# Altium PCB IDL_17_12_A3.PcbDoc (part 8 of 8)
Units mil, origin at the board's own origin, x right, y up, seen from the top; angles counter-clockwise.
Board outline 5119.97 x 10350 mil, 6 copper layers (Top Signal, 3.3 Volt, GND, 5 Volt, Split Plane, Bot Signal), stack 66.2 mil thick; 510 components, 178 nets, 2317 pads, 385 vias.
Unrouted connection lines stored in the file: 1.
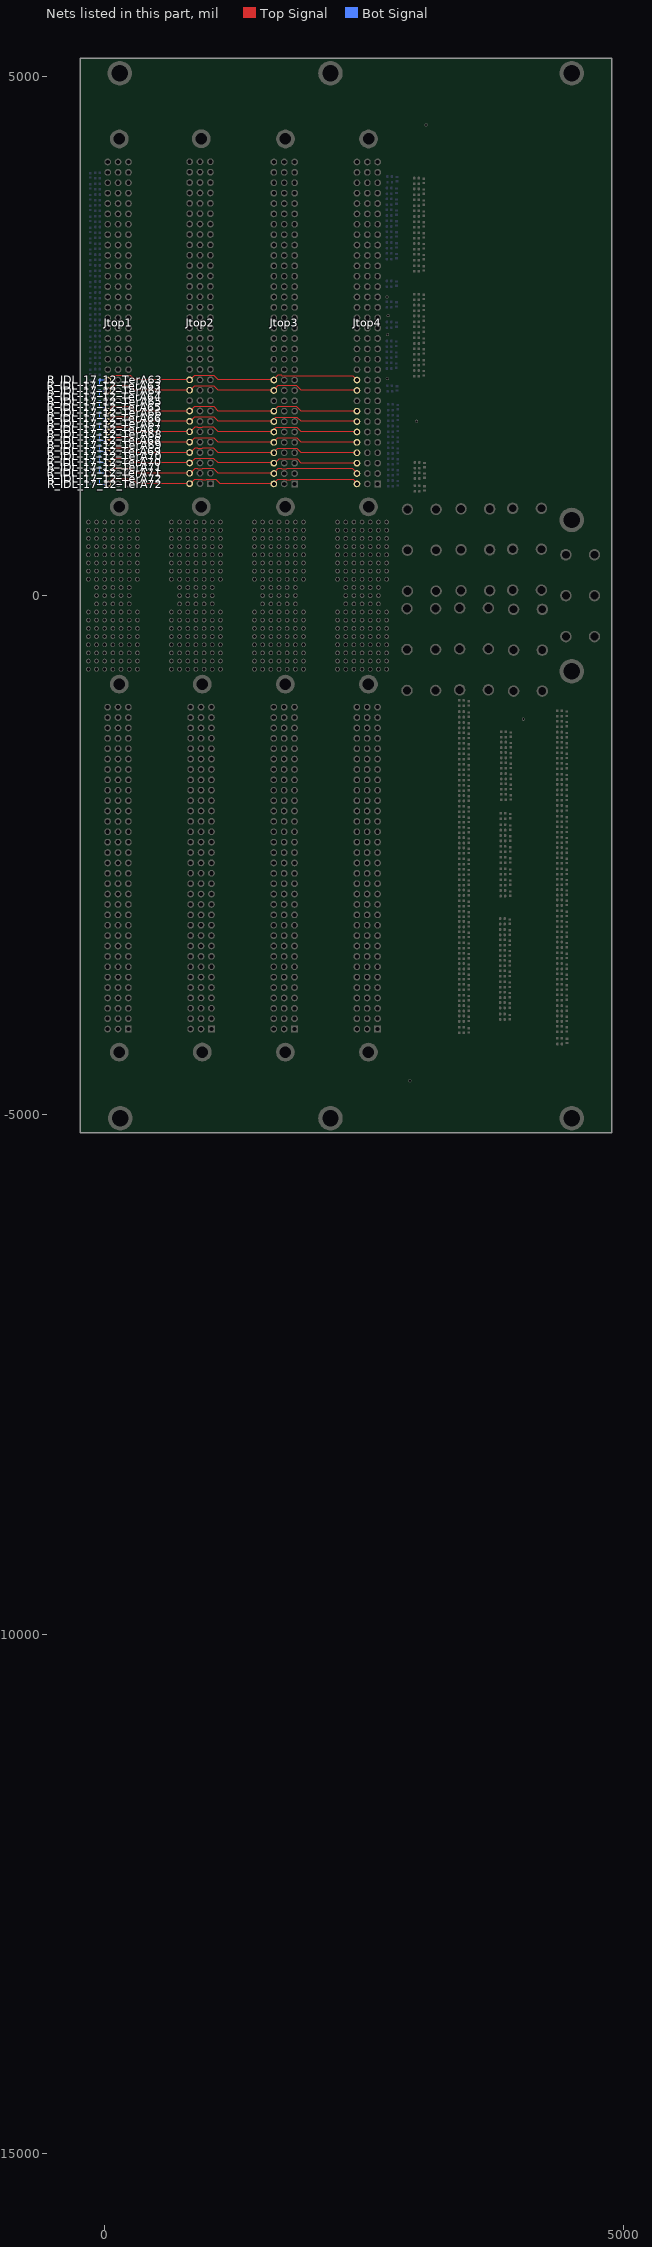
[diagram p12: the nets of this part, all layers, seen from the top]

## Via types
v1: diameter 25.59, hole 11.81, Top Signal to Bot Signal, 385 vias

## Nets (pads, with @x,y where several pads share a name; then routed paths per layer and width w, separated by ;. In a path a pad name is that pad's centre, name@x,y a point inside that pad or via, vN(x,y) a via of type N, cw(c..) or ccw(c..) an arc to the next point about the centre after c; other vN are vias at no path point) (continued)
JT63: Jtop1.C11 Jtop2.C11 Jtop3.C11 Jtop4.C11 R1R_IDL_17_12_TerA63.1 R2R_IDL_17_12_TerA63.2 | length 2657.8
  Top Signal w8: Jtop1.C11@28.79,2082.06 71.27,2124.54 246.39,2124.54 288.45,2082.48 828.72,2082.48 869.23,2122.99 893.67,2122.99 894.79,2121.87 941.58,2121.87 942.7,2122.99 1048.29,2122.99 1088.8,2082.48 1628.3,2082.48 1628.72,2082.06 1672.88,2126.22 1699.42,2126.22 1705.88,2119.76 2391.03,2119.76 Jtop4.C11@2428.72,2082.06
  Bot Signal w8: R2R_IDL_17_12_TerA63.2@-47.49,2021.93 -47.49,2076.07 R1R_IDL_17_12_TerA63.1@-46.62,2076.95 28.57,2076.95 Jtop1.C11@29.28,2076.24 ; Jtop4.C11@2429.28,2076.24 Jtop4.C11@2449.3,2076.24
JT64: Jtop1.C10 Jtop2.C10 Jtop3.C10 Jtop4.C10 R1R_IDL_17_12_TerA64.1 R2R_IDL_17_12_TerA64.2 | length 2662.5
  Top Signal w8: Jtop1.C10@28.79,1982.06 71.27,2024.54 246.39,2024.54 288.45,1982.48 828.72,1982.48 869.23,2022.99 1048.29,2022.99 1088.8,1982.48 1628.3,1982.48 1628.72,1982.06 1672.52,2025.86 1705.05,2025.86 1705.33,2025.58 1752.12,2025.58 1752.4,2025.86 1845,2025.86 1888.8,1982.06 Jtop4.C10@2428.72,1982.06
  Bot Signal w8: R2R_IDL_17_12_TerA64.2@-47.49,1916.93 -46.62,1944.23 R1R_IDL_17_12_TerA64.1@-46.62,1971.95 24.99,1971.95 Jtop1.C10@29.28,1976.24 ; Jtop4.C10@2429.28,1976.24 Jtop4.C10@2453.93,1976.24
JT65: Jtop1.C8 Jtop2.C8 Jtop3.C8 Jtop4.C8 R1R_IDL_17_12_TerA65.1 R2R_IDL_17_12_TerA65.2 | length 2672.6
  Top Signal w8: Jtop1.C8@28.79,1782.06 71.27,1824.54 246.39,1824.54 288.45,1782.48 828.72,1782.48 869.23,1822.99 1048.29,1822.99 1088.8,1782.48 1628.3,1782.48 1628.72,1782.06 1672.52,1825.86 1705.05,1825.86 1705.33,1825.58 1752.12,1825.58 1752.4,1825.86 1845,1825.86 1888.8,1782.06 Jtop4.C8@2428.72,1782.06
  Bot Signal w8: R1R_IDL_17_12_TerA65.1@-46.62,1866.95 -46.62,1812.81 R2R_IDL_17_12_TerA65.2@-47.49,1811.93 -6.41,1811.93 Jtop1.C8@29.28,1776.24 ; Jtop4.C8@2429.28,1776.24 Jtop4.C8@2449.77,1776.24
JT66: Jtop1.C7 Jtop2.C7 Jtop3.C7 Jtop4.C7 R1R_IDL_17_12_TerA66.1 R2R_IDL_17_12_TerA66.2 | length 2642.8
  Top Signal w8: Jtop1.C7@28.79,1682.06 71.27,1724.54 246.39,1724.54 288.45,1682.48 828.72,1682.48 867.06,1720.83 940.54,1720.83 941.62,1721.9 1049.38,1721.9 1088.8,1682.48 1609.02,1682.48 1645.37,1718.84 1852.02,1718.84 1888.8,1682.06 Jtop4.C7@2428.72,1682.06
  Bot Signal w8: R1R_IDL_17_12_TerA66.1@-46.62,1761.95 -46.62,1707.81 R2R_IDL_17_12_TerA66.2@-47.49,1706.93 -1.41,1706.93 Jtop1.C7@29.28,1676.24
JT67: Jtop1.C6 Jtop2.C6 Jtop3.C6 Jtop4.C6 R1R_IDL_17_12_TerA67.1 R2R_IDL_17_12_TerA67.2 | length 2672.9
  Top Signal w8: Jtop1.C6@28.79,1582.06 71.27,1624.54 246.39,1624.54 288.45,1582.48 828.72,1582.48 871.55,1625.31 891.35,1625.31 894.79,1621.87 941.58,1621.87 945.03,1625.31 1045.97,1625.31 1088.8,1582.48 1615.4,1582.48 1653.69,1620.77 1704.87,1620.77 1705.88,1619.76 1752.67,1619.76 1753.69,1620.77 1850.09,1620.77 1888.8,1582.06 Jtop4.C6@2428.72,1582.06
  Bot Signal w8: R1R_IDL_17_12_TerA67.1@-46.62,1656.95 -46.62,1629.23 -47.49,1628.36 R2R_IDL_17_12_TerA67.2@-47.49,1601.93 3.59,1601.93 Jtop1.C6@29.28,1576.24 ; Jtop4.C6@2429.28,1576.24 Jtop4.C6@2453.41,1576.24
JT68: Jtop1.C5 Jtop2.C5 Jtop3.C5 Jtop4.C5 R1R_IDL_17_12_TerA68.1 R2R_IDL_17_12_TerA68.2 | length 2660.1
  Top Signal w8: Jtop1.C5@28.79,1482.06 71.27,1524.54 246.39,1524.54 288.45,1482.48 828.72,1482.48 868.05,1521.81 1049.47,1521.81 1088.8,1482.48 1628.3,1482.48 1628.72,1482.06 1665.77,1519.11 1851.75,1519.11 1888.8,1482.06 Jtop4.C5@2428.72,1482.06
  Bot Signal w8: R1R_IDL_17_12_TerA68.1@-46.62,1551.95 -46.62,1524.23 -47.49,1523.36 R2R_IDL_17_12_TerA68.2@-47.49,1496.93 8.59,1496.93 Jtop1.C5@29.28,1476.24 ; Jtop4.C5@2429.28,1476.24 Jtop4.C5@2450.23,1476.24
JT69: Jtop1.C4 Jtop2.C4 Jtop3.C4 Jtop4.C4 R1R_IDL_17_12_TerA69.1 R2R_IDL_17_12_TerA69.2 | length 2642.3
  Top Signal w8: Jtop1.C4@28.79,1382.06 71.27,1424.54 246.39,1424.54 288.45,1382.48 828.72,1382.48 871.2,1424.96 891.7,1424.96 894.79,1421.87 941.58,1421.87 944.68,1424.96 1046.32,1424.96 1088.8,1382.48 1628.3,1382.48 1628.72,1382.06 1665.84,1419.18 1851.68,1419.18 1888.8,1382.06 Jtop4.C4@2428.72,1382.06
  Bot Signal w8: R1R_IDL_17_12_TerA69.1@-46.62,1446.95 -47.49,1446.07 R2R_IDL_17_12_TerA69.2@-47.49,1391.93 13.59,1391.93 Jtop1.C4@29.28,1376.24
JT70: Jtop1.C3 Jtop2.C3 Jtop3.C3 Jtop4.C3 R1R_IDL_17_12_TerA70.1 R2R_IDL_17_12_TerA70.2 | length 2641.2
  Top Signal w8: Jtop1.C3@28.79,1282.06 71.27,1324.54 246.39,1324.54 288.45,1282.48 828.72,1282.48 871.2,1324.96 891.7,1324.96 894.79,1321.87 941.58,1321.87 944.68,1324.96 1046.32,1324.96 1088.8,1282.48 1628.3,1282.48 1628.72,1282.06 1643.2,1282.06 1679.85,1318.72 1746.87,1318.72 1748.59,1317.01 1809.97,1317.01 1811.68,1318.72 1852.14,1318.72 1888.8,1282.06 Jtop4.C3@2428.72,1282.06
  Bot Signal w8: R1R_IDL_17_12_TerA70.1@-46.62,1341.95 -46.62,1287.81 R2R_IDL_17_12_TerA70.2@-47.49,1286.93 18.59,1286.93 Jtop1.C3@29.28,1276.24
JT71: Jtop1.C2 Jtop2.C2 Jtop3.C2 Jtop4.C2 R1R_IDL_17_12_TerA71.1 R2R_IDL_17_12_TerA71.2 | length 2669.1
  Top Signal w8: Jtop1.C2@28.79,1182.06 71.27,1224.54 246.39,1224.54 288.45,1182.48 828.72,1182.48 871.2,1224.96 891.7,1224.96 894.79,1221.87 941.58,1221.87 944.68,1224.96 1046.32,1224.96 1088.8,1182.48 1628.3,1182.48 1628.72,1182.06 1671.2,1224.54 1701.1,1224.54 1705.88,1219.76 1752.67,1219.76 1757.46,1224.54 2386.24,1224.54 Jtop4.C2@2428.72,1182.06
  Bot Signal w8: R1R_IDL_17_12_TerA71.1@-46.62,1236.95 -47.49,1236.07 R2R_IDL_17_12_TerA71.2@-47.49,1181.93 23.59,1181.93 Jtop1.C2@29.28,1176.24 ; Jtop4.C2@2429.28,1176.24 Jtop4.C2@2451.87,1176.24
JT72: Jtop1.C1 Jtop2.C1 Jtop3.C1 Jtop4.C1 R1R_IDL_17_12_TerA72.1 R2R_IDL_17_12_TerA72.2 | length 2647.7
  Top Signal w8: Jtop1.C1@28.79,1082.06 71.27,1124.54 265.41,1124.54 307.47,1082.48 828.72,1082.48 867.06,1120.83 935.78,1120.83 940.03,1116.58 977.32,1116.58 981.57,1120.83 1069.48,1120.83 1107.82,1082.48 1628.3,1082.48 1628.72,1082.06 1665.37,1118.72 1746.87,1118.72 1749.27,1116.32 1790.26,1116.32 1792.66,1118.72 2392.07,1118.72 Jtop4.C1@2428.72,1082.06
  Bot Signal w8: R1R_IDL_17_12_TerA72.1@-46.63,1126.4 -46.63,1072.16 R2R_IDL_17_12_TerA72.2@-46.36,1071.89 24.93,1071.89 Jtop1.C1@29.28,1076.24 ; Jtop4.C1@2429.28,1063.33 Jtop4.C1@2429.28,1076.24
pads on no net: Jbot1.33 Jbot1.34 Jbot2.33 Jbot2.34 Jbot3.33 Jbot3.34 Jbot4.33 Jbot4.34 JMid1.32 JMid1.33 JMid1.34 JMid1.35 JMid1.51 JMid1.52 JMid1.53 JMid1.54 JMid1.89 JMid1.90 JMid1.91 JMid1.92 JMid1.102 JMid1.103 JMid1.104 JMid1.106 JMid1.108 JMid1.109 JMid1.110 JMid1.111 JMid2.32 JMid2.33 JMid2.34 JMid2.35 JMid2.51 JMid2.52 JMid2.53 JMid2.54 JMid2.89 JMid2.90 JMid2.91 JMid2.92 JMid2.102 JMid2.103 JMid2.104 JMid2.106 JMid2.108 JMid2.109 JMid2.110 JMid2.111 JMid3.32 JMid3.33 JMid3.34 JMid3.35 JMid3.51 JMid3.52 JMid3.53 JMid3.54 JMid3.89 JMid3.90 JMid3.91 JMid3.92 JMid3.102 JMid3.103 JMid3.104 JMid3.106 JMid3.108 JMid3.109 JMid3.110 JMid3.111 JMid4.32 JMid4.33 JMid4.34 JMid4.35 JMid4.51 JMid4.52 JMid4.53 JMid4.54 JMid4.89 JMid4.90 JMid4.91 JMid4.92 JMid4.102 JMid4.103 JMid4.104 JMid4.106 JMid4.108 JMid4.109 JMid4.110 JMid4.111 Jtop1.33 Jtop1.34 Jtop2.33 Jtop2.34 Jtop3.33 Jtop3.34 Jtop4.33 Jtop4.34

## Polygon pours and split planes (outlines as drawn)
3V3 on 3.3 Volt (split plane): 4862.88,-5152.9 -215.91,-5152.9 -215.91,5156.9 4862.88,5156.9
GND on GND (split plane): 4862.88,-5152.9 -216.9,-5152.9 -216.9,5156.9 4862.88,5156.9
5V on 5 Volt (split plane): 4862.88,-5152.9 -215.91,-5152.9 -215.91,5156.9 4862.88,5156.9
no net on Split Plane (split plane): 4810.9,4255.78 4810.9,-471.58 4772.4,-510.07 4394.09,-510.07 4326.93,-442.91 4326.93,4079.79 4326.59,4082.4 4325.58,4084.84 4323.98,4086.92 4221.03,4189.87 4218.94,4191.48 4216.51,4192.48 4213.9,4192.83 2648,4192.83 2645.39,4192.48 2642.96,4191.48 2640.87,4189.87 2439.11,3988.11 2411.18,3988.11 2410.24,3988.5 2407.63,3988.85 2302.7,3988.85 2109.93,4181.62 2107.84,4183.22 2105.41,4184.23 2102.8,4184.57 1830.07,4184.57 1827.46,4184.23 1826.75,4183.93 1825.03,4183.22 1822.94,4181.62 1644.3,4002.98 1481.72,4002.98 1306.23,4178.47 1304.15,4180.07 1301.71,4181.08 1299.1,4181.42 1011.18,4181.42 1008.57,4181.08 1007.85,4180.78 1006.13,4180.07 1004.05,4178.47 867.19,4041.61 813.48,3987.91 728.16,3987.91 533.24,4182.83 531.15,4184.44 528.71,4185.44 526.1,4185.79 221.29,4185.79 218.68,4185.44 217.47,4184.94 216.25,4184.44 214.16,4182.83 24.04,3992.72 -74.26,4091.02 -74.26,4582.63 87.1,4744 4322.68,4744
no net on Split Plane (split plane): 4306.76,4075.61 4306.76,-27.33 3811.52,-27.33 3712.49,71.7 3712.49,1120.64 3712.14,1123.26 3711.13,1125.69 3709.53,1127.78 3254.43,1582.88 3252.34,1584.48 3249.91,1585.49 3247.3,1585.83 29.28,1585.83 27.79,1585.64 27.4,1586.57 25.8,1588.65 -82.28,1696.74 -84.37,1698.34 -84.67,1698.47 -84.67,3851.44 -84.37,3851.57 -82.28,3853.17 30.91,3966.37 31.89,3966.49 34.32,3967.5 36.41,3969.1 38.01,3971.19 39.02,3973.63 39.37,3976.24 39.02,3978.85 38.93,3979.07 225.47,4165.62 521.93,4165.62 716.85,3970.69 718.94,3969.08 720.37,3968.49 721.38,3968.08 723.99,3967.73 817.66,3967.73 820.27,3968.08 822.71,3969.08 824.79,3970.69 881.45,4027.35 1015.36,4161.25 1294.92,4161.25 1470.41,3985.76 1472.5,3984.16 1474.94,3983.15 1477.55,3982.8 1653.03,3982.8 1655.64,3983.15 1658.07,3984.16 1660.16,3985.76 1661.76,3987.85 1662.77,3990.28 1663.12,3992.89 1663.07,3993.22 1834.25,4164.4 2098.62,4164.4 2291.39,3971.63 2293.48,3970.02 2294.7,3969.52 2295.91,3969.02 2298.52,3968.67 2404.81,3968.67 2405.75,3968.28 2408.36,3967.94 2443.29,3967.94 2445.9,3968.28 2448.33,3969.29 2450.42,3970.9 2652.18,4172.65 4209.72,4172.65
-3V3 on Split Plane (split plane): 2758.31,99.98 2758.31,39.27 2758.66,36.66 2759.67,34.23 2761.27,32.14 2848.41,-55 2849.39,-55.75 2850.37,-56.53 2850.44,-56.56 2850.5,-56.6 2851.65,-57.08 2852.79,-57.57 2852.86,-57.58 2852.93,-57.61 2854.16,-57.77 2855.39,-57.95 2908.87,-58.74 2908.94,-58.73 2909.02,-58.74 3325.16,-58.74 3327.77,-58.4 3330.2,-57.39 3332.29,-55.79 3427.02,38.94 3542.81,-76.85 3542.81,-768.37 3054.61,-1256.57 229.31,-1256.57 -147.39,-879.87 -147.39,153.42 -73.52,227.3 2631,227.3
no net on Split Plane (split plane): -85,1467.77 2776.75,1467.77 3421.86,822.66 3421.86,62.31 3320.98,-38.57 2909.09,-38.57 2859.78,-37.84 2778.49,43.45 2778.49,104.16 2778.14,106.77 2777.14,109.21 2775.53,111.29 2642.31,244.52 2640.22,246.12 2637.79,247.13 2635.18,247.47 -75.6,247.47 -149.83,321.7 -149.83,1402.94 -149.84,1403.04 -85.1,1467.78
no net on Split Plane (split plane): 4862.88,-5152.9 -216.9,-5152.9 -216.9,5156.9 4862.88,5156.9

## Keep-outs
Keep-Out Layer:
  lines w20: -237,-5173 -237,5177

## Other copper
3.3 Volt (plane layer: these items are gaps in the copper):
  lines w20: -226,-5162 -226,5166
5 Volt (plane layer: these items are gaps in the copper):
  lines w20: -226,-5162 -226,5166
Split Plane (plane layer: these items are gaps in the copper):
  lines w20: -161.26,1405.89 -86.34,1480.81 ; -159.92,1402.94 -159.92,317.52 -79.78,237.38 2635.18,237.38 2768.4,104.16 2768.4,39.27 2855.54,-47.87 2909.02,-48.66 3325.16,-48.66 3431.95,58.14 3431.95,826.84 2780.93,1477.86 -85,1477.86 ; -94.76,1692.04 -94.76,3862.73 ; -89.42,1689.61 18.67,1581.52 ; -89.42,3860.3 26.52,3976.24 29.28,3976.24 ; -78.74,236.34 -157.48,157.6 -157.48,-884.05 225.13,-1266.66 3058.78,-1266.66 3552.9,-772.55 3552.9,-72.67 3431.95,48.27 ; 23.75,3978.15 221.29,4175.7 526.1,4175.7 723.99,3977.82 817.66,3977.82 874.32,4034.48 1011.18,4171.33 1299.1,4171.33 1477.55,3992.89 1653.03,3992.89 ; 23.75,3978.75 -84.35,4086.84 -84.35,4586.81 82.92,4754.08 4326.85,4754.08 4820.98,4259.96 4820.98,-475.75 4776.57,-520.16 4389.91,-520.16 4316.84,-447.09 4316.84,4079.79 4213.9,4182.74 2648,4182.74 2443.29,3978.03 2408.36,3978.03 2407.63,3978.76 2298.52,3978.76 2102.8,4174.49 1830.07,4174.49 1650.75,3995.17 ; 29.28,1575.75 3247.3,1575.75 3702.4,1120.64 3702.4,67.52 3807.34,-37.42 4315.22,-37.42

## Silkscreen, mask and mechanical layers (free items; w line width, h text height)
Top Overlay:
  drawing of 160 lines, arcs and shapes, not listed
  text "IDL_17_12 / VME Backplae Rev.A / Designer: Jose Duron" at 3223.2,-4687.76 h60
  text "IDL" at 3398.32,-4827.7 h50
  text "Instrumentation" at 3398.32,-4877.7 h25
  text "Development" at 3398.32,-4917.7 h25
  text "Lab" at 3398.32,-4957.7 h25
Mechanical 2:
  drawing of 252 lines, arcs and shapes, not listed
  text "1" at -13904.31,8306.83 h35
  text "2" at -11929.31,8306.83 h35
  text "3" at -9954.31,8306.83 h35
  text "4" at -7979.31,8306.83 h35
  text "5" at -6004.31,8306.83 h35
  text "6" at -4029.31,8306.83 h35
  text "7" at -2054.31,8306.83 h35
  text "8" at -79.31,8306.83 h35
  text "1" at -14184.39,7643.66 h35
  text "2" at -12209.39,7643.66 h35
  text "3" at -10234.39,7643.66 h35
  text "4" at -8259.39,7643.66 h35
  text "5" at -6284.39,7643.66 h35
  text "6" at -4309.39,7643.66 h35
  text "7" at -2334.39,7643.66 h35
  text "8" at -359.39,7643.66 h35
  text "A" at -14846.86,7349.68 h35
  text "A" at 853.15,7349.68 h35
  text "1" at 2612.73,6786.27 h35
  text "2" at 4587.73,6786.27 h35
  text "3" at 6562.73,6786.27 h35
  text "4" at 8537.73,6786.27 h35
  text "5" at 10512.73,6786.27 h35
  text "6" at 12487.73,6786.27 h35
  text "7" at 14462.73,6786.27 h35
  text "8" at 16437.73,6786.27 h35
  text "A" at -15126.93,6686.51 h35
  text "A" at 573.07,6686.51 h35
  text "1" at -13620.84,6299.24 h35
  text "2" at -11645.84,6299.24 h35
  text "3" at -9670.84,6299.24 h35
  text "4" at -7695.84,6299.24 h35
  text "5" at -5720.84,6299.24 h35
  text "6" at -3745.84,6299.24 h35
  text "7" at -1770.84,6299.24 h35
  text "8" at 204.16,6299.24 h35
  text "A" at 1670.18,5829.12 h35
  text "A" at 17370.18,5829.12 h35
  text "B" at -14846.86,5436.35 h35
  text "B" at 853.15,5436.35 h35
  text "A" at -14563.38,5342.09 h35
  text "A" at 1136.62,5342.09 h35
  text "B" at -15126.93,4773.18 h35
  text "B" at 573.07,4773.18 h35
  text "B" at 1670.18,3915.79 h35
  text "B" at 17370.18,3915.79 h35
  text "C" at -14851.9,3523.01 h35
  text "C" at 848.1,3523.01 h35
  text "B" at -14563.38,3428.76 h35
  text "B" at 1136.62,3428.76 h35
  text "C" at -15131.98,2859.84 h35
  text "C" at 568.02,2859.84 h35
  text "C" at 1665.14,2002.45 h35
  text "C" at 17365.14,2002.45 h35
  text "D" at -14851.9,1609.68 h35
  text "D" at 848.1,1609.68 h35
  text "1" at -9275.06,1545.98 h35
  text "2" at -7300.06,1545.98 h35
  text "3" at -5325.06,1545.98 h35
  text "4" at -3350.06,1545.98 h35
  text "5" at -1375.06,1545.98 h35
  text "6" at 599.94,1545.98 h35
  text "7" at 2574.94,1545.98 h35
  text "8" at 4549.94,1545.98 h35
  text "C" at -14568.43,1515.43 h35
  text "C" at 1131.57,1515.43 h35
  text "D" at -15131.98,946.51 h35
  text "D" at 568.02,946.51 h35
  text "1" at 5628.19,870.06 h35
  text "2" at 7603.19,870.06 h35
  text "3" at 9578.19,870.06 h35
  text "4" at 11553.19,870.06 h35
  text "5" at 13528.19,870.06 h35
  text "6" at 15503.19,870.06 h35
  text "7" at 17478.19,870.06 h35
  text "8" at 19453.19,870.06 h35
  text "A" at -10217.6,588.82 h35
  text "A" at 5482.4,588.82 h35
  text "D" at 1665.14,89.12 h35
  text "D" at 17365.14,89.12 h35
  text "A" at 4685.65,-87.09 h35
  text "A" at 20385.65,-87.09 h35
  text "E" at -14846.86,-303.65 h35
  text "E" at 853.15,-303.65 h35
  text "D" at -14568.43,-397.91 h35
  text "D" at 1131.57,-397.91 h35
  text "E" at -15126.93,-966.82 h35
  text "E" at 573.07,-966.82 h35
  text "B" at -10217.6,-1324.51 h35
  text "B" at 5482.4,-1324.51 h35
  text "E" at 1670.18,-1824.21 h35
  text "E" at 17370.18,-1824.21 h35
  text "B" at 4685.65,-2000.42 h35
  text "B" at 20385.65,-2000.42 h35
  text "F" at -14846.86,-2216.99 h35
  text "F" at 853.15,-2216.99 h35
  text "E" at -14563.38,-2311.24 h35
  text "E" at 1136.62,-2311.24 h35
  text "Designer:" at -5836.63,-2373.65 h100
  text ".Designer" at -5271.63,-2378.65 h100
  text "Revision:" at -4331.63,-2378.65 h100
  text ".RevNum" at -3771.63,-2378.65 h100
  text "File:" at -3331.63,-2378.65 h100
  text ".Pcb_File_Name_No_Path" at -3131.63,-2378.65 h100
  text "Sheet  1 of  1" at -1736.63,-2378.65 h100
  text "Code:" at -1016.63,-2423.65 h100
  text "Drawn By:" at -5836.63,-2493.65 h100
  text ".Drawn_By" at -5271.63,-2493.65 h100
  text "Modif. Date:" at -4331.63,-2498.65 h100
  text "Date" at -3826.63,-2498.65 h100
  text "Variant:" at -3331.63,-2498.65 h100
  text ".VariantName" at -2966.63,-2498.65 h100
  text "ID:" at -1011.63,-2603.65 h100
  text "Approved By:" at -5836.63,-2613.65 h100
  text ".Approved_By" at -5271.63,-2613.65 h100
  text ".Print_Date" at -3884.23,-2618.06 h100
  text "Print Date:" at -4331.63,-2618.65 h100
  text "Signature:" at -3331.63,-2618.65 h100
  text "Size:  A3 H" at -1736.63,-2618.65 h100
  text "Title:" at -5836.63,-2743.65 h100
  text "University of Hawaii at Manoa" at -1010.21,-2751.92 h100
  text "High Energy Physics Group" at -1010.21,-2850.35 h100
  text "F" at -15126.93,-2880.16 h35
  text "F" at 573.07,-2880.16 h35
  text ".Printout_Name" at -5611.63,-2883.65 h160
  text "Instrumentation Development Laboratory" at -1010.21,-2952.71 h100
  text "Designer:" at -6116.71,-3036.82 h100
  text ".Designer" at -5551.71,-3041.82 h100
  text "Revision:" at -4611.71,-3041.82 h100
  text ".RevNum" at -4051.71,-3041.82 h100
  text "File:" at -3611.71,-3041.82 h100
  text ".Pcb_File_Name_No_Path" at -3411.71,-3041.82 h100
  text "Sheet  1 of  1" at -2016.71,-3041.82 h100
  text "1" at -13904.31,-3073.17 h35
  text "2" at -11929.31,-3073.17 h35
  text "3" at -9954.31,-3073.17 h35
  text "4" at -7979.31,-3073.17 h35
  text "5" at -6004.31,-3073.17 h35
  text "6" at -4029.31,-3073.17 h35
  text "7" at -2054.31,-3073.17 h35
  text "8" at -79.31,-3073.17 h35
  text "Code:" at -1296.71,-3086.82 h100
  text "Drawn By:" at -6116.71,-3156.82 h100
  text ".Drawn_By" at -5551.71,-3156.82 h100
  text "Modif. Date:" at -4611.71,-3161.82 h100
  text "Date" at -4106.71,-3161.82 h100
  text "Variant:" at -3611.71,-3161.82 h100
  text ".VariantName" at -3246.71,-3161.82 h100
  text "C" at -10222.65,-3237.84 h35
  text "C" at 5477.35,-3237.84 h35
  text "ID:" at -1291.71,-3266.82 h100
  text "Approved By:" at -6116.71,-3276.82 h100
  text ".Approved_By" at -5551.71,-3276.82 h100
  text ".Print_Date" at -4164.31,-3281.23 h100
  text "Print Date:" at -4611.71,-3281.82 h100
  text "Signature:" at -3611.71,-3281.82 h100
  text "Size:  A3 H" at -2016.71,-3281.82 h100
  text "Title:" at -6116.71,-3406.82 h100
  text "University of Hawaii at Manoa" at -1290.29,-3415.09 h100
  text "High Energy Physics Group" at -1290.29,-3513.52 h100
  text ".Printout_Name" at -5891.71,-3546.82 h160
  text "Instrumentation Development Laboratory" at -1290.29,-3615.88 h100
  text "1" at -14184.39,-3736.34 h35
  text "2" at -12209.39,-3736.34 h35
  text "3" at -10234.39,-3736.34 h35
  text "4" at -8259.39,-3736.34 h35
  text "5" at -6284.39,-3736.34 h35
  text "6" at -4309.39,-3736.34 h35
  text "7" at -2334.39,-3736.34 h35
  text "8" at -359.39,-3736.34 h35
  text "F" at 1670.18,-3737.55 h35
  text "F" at 17370.18,-3737.55 h35
  text "Designer:" at 10680.41,-3894.21 h100
  text ".Designer" at 11245.41,-3899.21 h100
  text "Revision:" at 12185.41,-3899.21 h100
  text ".RevNum" at 12745.41,-3899.21 h100
  text "File:" at 13185.41,-3899.21 h100
  text ".Pcb_File_Name_No_Path" at 13385.41,-3899.21 h100
  text "Sheet  1 of  1" at 14780.41,-3899.21 h100
  text "C" at 4680.6,-3913.75 h35
  text "C" at 20380.6,-3913.75 h35
  text "Code:" at 15500.41,-3944.21 h100
  text "Drawn By:" at 10680.41,-4014.21 h100
  text ".Drawn_By" at 11245.41,-4014.21 h100
  text "Modif. Date:" at 12185.41,-4019.21 h100
  text "Date" at 12690.41,-4019.21 h100
  text "Variant:" at 13185.41,-4019.21 h100
  text ".VariantName" at 13550.41,-4019.21 h100
  text "ID:" at 15505.41,-4124.21 h100
  text "Approved By:" at 10680.41,-4134.21 h100
  text ".Approved_By" at 11245.41,-4134.21 h100
  text "Print Date:" at 12185.41,-4139.21 h100
  text ".Print_Date" at 12632.81,-4138.62 h100
  text "Signature:" at 13185.41,-4139.21 h100
  text "Size:  A3 H" at 14780.41,-4139.21 h100
  text "F" at -14563.38,-4224.57 h35
  text "F" at 1136.62,-4224.57 h35
  text "Title:" at 10680.41,-4264.21 h100
  text "University of Hawaii at Manoa" at 15506.82,-4272.48 h100
  text "High Energy Physics Group" at 15506.82,-4370.91 h100
  text "Designer:" at -5553.16,-4381.24 h100
  text ".Designer" at -4988.16,-4386.24 h100
  text "Revision:" at -4048.16,-4386.24 h100
  text ".RevNum" at -3488.16,-4386.24 h100
  text "File:" at -3048.16,-4386.24 h100
  text ".Pcb_File_Name_No_Path" at -2848.16,-4386.24 h100
  text "Sheet  1 of  1" at -1453.16,-4386.24 h100
  text ".Printout_Name" at 10905.41,-4404.21 h160
  text "Code:" at -733.16,-4431.24 h100
  text "Instrumentation Development Laboratory" at 15506.82,-4473.27 h100
  text "Drawn By:" at -5553.16,-4501.24 h100
  text ".Drawn_By" at -4988.16,-4501.24 h100
  text "Modif. Date:" at -4048.16,-4506.24 h100
  text "Date" at -3543.16,-4506.24 h100
  text "Variant:" at -3048.16,-4506.24 h100
  text ".VariantName" at -2683.16,-4506.24 h100
  text "1" at 2612.73,-4593.73 h35
  text "2" at 4587.73,-4593.73 h35
  text "3" at 6562.73,-4593.73 h35
  text "4" at 8537.73,-4593.73 h35
  text "5" at 10512.73,-4593.73 h35
  text "6" at 12487.73,-4593.73 h35
  text "7" at 14462.73,-4593.73 h35
  text "8" at 16437.73,-4593.73 h35
  text "ID:" at -728.16,-4611.24 h100
  text "Approved By:" at -5553.16,-4621.24 h100
  text ".Approved_By" at -4988.16,-4621.24 h100
  text "Print Date:" at -4048.16,-4626.24 h100
  text ".Print_Date" at -3600.76,-4625.65 h100
  text "Signature:" at -3048.16,-4626.24 h100
  text "Size:  A3 H" at -1453.16,-4626.24 h100
  text "Title:" at -5553.16,-4751.24 h100
  text "University of Hawaii at Manoa" at -726.74,-4759.51 h100
  text "High Energy Physics Group" at -726.74,-4857.93 h100
  text ".Printout_Name" at -5328.16,-4891.24 h160
  text "Instrumentation Development Laboratory" at -726.74,-4960.3 h100
  text "1" at -13620.84,-5080.76 h35
  text "2" at -11645.84,-5080.76 h35
  text "3" at -9670.84,-5080.76 h35
  text "4" at -7695.84,-5080.76 h35
  text "5" at -5720.84,-5080.76 h35
  text "6" at -3745.84,-5080.76 h35
  text "7" at -1770.84,-5080.76 h35
  text "8" at 204.16,-5080.76 h35
  text "D" at -10222.65,-5151.18 h35
  text "D" at 5477.35,-5151.18 h35
  text "D" at 4680.6,-5827.09 h35
  text "D" at 20380.6,-5827.09 h35
  text "E" at -10217.6,-7064.51 h35
  text "E" at 5482.4,-7064.51 h35
  text "E" at 4685.65,-7740.42 h35
  text "E" at 20385.65,-7740.42 h35
  text "F" at -10217.6,-8977.84 h35
  text "F" at 5482.4,-8977.84 h35
  text "Designer:" at -1207.38,-9134.51 h100
  text ".Designer" at -642.38,-9139.51 h100
  text "Revision:" at 297.62,-9139.51 h100
  text ".RevNum" at 857.62,-9139.51 h100
  text "File:" at 1297.62,-9139.51 h100
  text ".Pcb_File_Name_No_Path" at 1497.62,-9139.51 h100
  text "Sheet  1 of  1" at 2892.62,-9139.51 h100
  text "Code:" at 3612.62,-9184.51 h100
  text "Drawn By:" at -1207.38,-9254.51 h100
  text ".Drawn_By" at -642.38,-9254.51 h100
  text "Modif. Date:" at 297.62,-9259.51 h100
  text "Date" at 802.62,-9259.51 h100
  text "Variant:" at 1297.62,-9259.51 h100
  text ".VariantName" at 1662.62,-9259.51 h100
  text "ID:" at 3617.62,-9364.51 h100
  text "Approved By:" at -1207.38,-9374.51 h100
  text ".Approved_By" at -642.38,-9374.51 h100
  text ".Print_Date" at 745.02,-9378.92 h100
  text "Print Date:" at 297.62,-9379.51 h100
  text "Signature:" at 1297.62,-9379.51 h100
  text "Size:  A3 H" at 2892.62,-9379.51 h100
  text "Title:" at -1207.38,-9504.51 h100
  text "University of Hawaii at Manoa" at 3619.04,-9512.78 h100
  text "High Energy Physics Group" at 3619.04,-9611.2 h100
  text ".Printout_Name" at -982.38,-9644.51 h160
  text "F" at 4685.65,-9653.75 h35
  text "F" at 20385.65,-9653.75 h35
  text "Instrumentation Development Laboratory" at 3619.04,-9713.56 h100
  text "Designer:" at 13695.87,-9810.42 h100
  text ".Designer" at 14260.87,-9815.42 h100
  text "Revision:" at 15200.87,-9815.42 h100
  text ".RevNum" at 15760.87,-9815.42 h100
  text "File:" at 16200.87,-9815.42 h100
  text ".Pcb_File_Name_No_Path" at 16400.87,-9815.42 h100
  text "Sheet  1 of  1" at 17795.87,-9815.42 h100
  text "1" at -9275.06,-9834.02 h35
  text "2" at -7300.06,-9834.02 h35
  text "3" at -5325.06,-9834.02 h35
  text "4" at -3350.06,-9834.02 h35
  text "5" at -1375.06,-9834.02 h35
  text "6" at 599.94,-9834.02 h35
  text "7" at 2574.94,-9834.02 h35
  text "8" at 4549.94,-9834.02 h35
  text "Code:" at 18515.87,-9860.42 h100
  text "Drawn By:" at 13695.87,-9930.42 h100
  text ".Drawn_By" at 14260.87,-9930.42 h100
  text "Modif. Date:" at 15200.87,-9935.42 h100
  text "Date" at 15705.87,-9935.42 h100
  text "Variant:" at 16200.87,-9935.42 h100
  text ".VariantName" at 16565.87,-9935.42 h100
  text "ID:" at 18520.87,-10040.42 h100
  text "Approved By:" at 13695.87,-10050.42 h100
  text ".Approved_By" at 14260.87,-10050.42 h100
  text "Print Date:" at 15200.87,-10055.42 h100
  text ".Print_Date" at 15648.27,-10054.83 h100
  text "Signature:" at 16200.87,-10055.42 h100
  text "Size:  A3 H" at 17795.87,-10055.42 h100
  text "Title:" at 13695.87,-10180.42 h100
  text "University of Hawaii at Manoa" at 18522.29,-10188.69 h100
  text "High Energy Physics Group" at 18522.29,-10287.12 h100
  text ".Printout_Name" at 13920.87,-10320.42 h160
  text "Instrumentation Development Laboratory" at 18522.29,-10389.48 h100
  text "1" at 5628.19,-10509.94 h35
  text "2" at 7603.19,-10509.94 h35
  text "3" at 9578.19,-10509.94 h35
  text "4" at 11553.19,-10509.94 h35
  text "5" at 13528.19,-10509.94 h35
  text "6" at 15503.19,-10509.94 h35
  text "7" at 17478.19,-10509.94 h35
  text "8" at 19453.19,-10509.94 h35
Board Outline:
  lines w20: -237,-5173 4880.39,-5173 4880.39,5174.4 4880.55,5174.55 -234.55,5174.55 -237,5177 -237,-5173
Sheet Top:
  lines w3.9: -2026.33,-3719.49 -1926.33,-3719.49 ; -2026.33,-1806.16 -1926.33,-1806.16 ; -2026.33,107.18 -1926.33,107.18 ; -2026.33,2020.51 -1926.33,2020.51 ; -2026.33,3933.84 -1926.33,3933.84 ; -51.33,-5632.82 -51.33,-5532.82 ; -51.33,5747.18 -51.33,5847.18 ; 1923.67,-5632.82 1923.67,-5532.82 ; 1923.67,5747.18 1923.67,5847.18 ; 3898.67,-5632.82 3898.67,-5532.82 ; 3898.67,5747.18 3898.67,5847.18 ; 5873.67,-5632.82 5873.67,-5532.82 ; 5873.67,5747.18 5873.67,5847.18 ; 7848.67,-5632.82 7848.67,-5532.82 ; 7848.67,5747.18 7848.67,5847.18 ; 9823.67,-5632.82 9823.67,-5532.82 ; 9823.67,5747.18 9823.67,5847.18 ; 11798.67,-5632.82 11798.67,-5532.82 ; 11798.67,5747.18 11798.67,5847.18 ; 13673.67,-3719.49 13773.67,-3719.49 ; 13673.67,-1806.16 13773.67,-1806.16 ; 13673.67,107.18 13773.67,107.18 ; 13673.67,2020.51 13773.67,2020.51 ; 13673.67,3933.84 13773.67,3933.84 ; -2026.33,-5632.73 13773.58,-5632.73 13773.58,5847.18 -2026.33,5847.18 -2026.33,-5632.73 ; -1926.07,-5533.02 13673.32,-5533.02 13673.32,5747.47 -1926.07,5747.47 -1926.07,-5533.02
  lines w3.94: 6983.67,-5533.02 6983.67,-4822.82 13673.32,-4822.82 ; 6983.67,-5182.06 13673.67,-5182.06 ; 6983.67,-5062.82 11803.67,-5062.82 ; 6983.67,-4942.82 11803.67,-4942.82 ; 8488.67,-5182.06 8488.67,-4822.82 ; 9488.67,-5182.06 9488.67,-4822.82 ; 11078.67,-5182.06 11078.67,-4822.82 ; 11803.67,-5533.02 11803.67,-4822.82 ; 11803.67,-5002.82 13673.32,-5002.82
  text "1" at -1059.01,5767.66 h35
  text "2" at 915.99,5767.66 h35
  text "3" at 2890.99,5767.66 h35
  text "4" at 4865.99,5767.66 h35
  text "5" at 6840.99,5767.66 h35
  text "6" at 8815.99,5767.66 h35
  text "7" at 10790.99,5767.66 h35
  text "8" at 12765.99,5767.66 h35
  text "A" at -2001.56,4810.51 h35
  text "A" at 13698.45,4810.51 h35
  text "B" at -2001.56,2897.18 h35
  text "B" at 13698.45,2897.18 h35
  text "C" at -2006.6,983.84 h35
  text "C" at 13693.4,983.84 h35
  text "D" at -2006.6,-929.49 h35
  text "D" at 13693.4,-929.49 h35
  text "E" at -2001.56,-2842.82 h35
  text "E" at 13698.45,-2842.82 h35
  text "F" at -2001.56,-4756.16 h35
  text "F" at 13698.45,-4756.16 h35
  text "Designer:" at 7008.67,-4912.82 h100
  text ".Designer" at 7573.67,-4917.82 h100
  text "Revision:" at 8513.67,-4917.82 h100
  text ".RevNum" at 9073.67,-4917.82 h100
  text "File:" at 9513.67,-4917.82 h100
  text ".Pcb_File_Name_No_Path" at 9713.67,-4917.82 h100
  text "Sheet  1 of  1" at 11108.67,-4917.82 h100
  text "Code:" at 11828.67,-4962.82 h100
  text "Drawn By:" at 7008.67,-5032.82 h100
  text ".Drawn_By" at 7573.67,-5032.82 h100
  text "Modif. Date:" at 8513.67,-5037.82 h100
  text "Date" at 9018.67,-5037.82 h100
  text "Variant:" at 9513.67,-5037.82 h100
  text ".VariantName" at 9878.67,-5037.82 h100
  text "ID:" at 11833.67,-5142.82 h100
  text "Approved By:" at 7008.67,-5152.82 h100
  text ".Approved_By" at 7573.67,-5152.82 h100
  text ".Print_Date" at 8961.07,-5157.23 h100
  text "Print Date:" at 8513.67,-5157.82 h100
  text "Signature:" at 9513.67,-5157.82 h100
  text "Size:  A3 H" at 11108.67,-5157.82 h100
  text "Title:" at 7008.67,-5282.82 h100
  text "University of Hawaii at Manoa" at 11835.08,-5291.09 h100
  text "High Energy Physics Group" at 11835.08,-5389.52 h100
  text ".Printout_Name" at 7233.67,-5422.82 h160
  text "Instrumentation Development Laboratory" at 11835.08,-5491.88 h100
  text "1" at -1059.01,-5612.34 h35
  text "2" at 915.99,-5612.34 h35
  text "3" at 2890.99,-5612.34 h35
  text "4" at 4865.99,-5612.34 h35
  text "5" at 6840.99,-5612.34 h35
  text "6" at 8815.99,-5612.34 h35
  text "7" at 10790.99,-5612.34 h35
  text "8" at 12765.99,-5612.34 h35
Drill Drawing:
  drawing of 468 lines, arcs and shapes, not listed
  text "Notes:" at 7727.76,3850.27 h130
  text "1. Board shall be fabricated - performace class II as per IPC-6011 and IPC6012" at 7727.76,3725.27 h100
  text "2.All of bottom edge and sides edges up to 3.2mm of PCB needs to be plated with 35um copper." at 7727.76,3600.27 h100
  text "3. Silkscreen printed on both sides" at 7727.76,3493.78 h100
  text "4. Material: high temperature FR4 class epoxy glass rated UL94V-0. UL symbol and rating shall be marked farside" at 7727.76,3368.78 h100
  text "35um copper for external and internal layers" at 7827.78,3268.78 h100
  text "Must be RoHS compliant and survive a lead-free assembly max reflow of 260 deg C (5 passes)" at 7827.76,3168.78 h100
  text "Td rating: >340 deg C" at 7877.76,3043.78 h100
  text "Tg = 150 deg C (min)" at 7881.79,2933.52 h100
  text "5. Solder mask: SMOBC per IPC-SM-840C, class T must be Rohs compliant, 0.001\" max measured over bare copper plating," at 7727.76,2823.7 h100
  text "must clear all lands as indicated on gerber solder mask layers, color= GREEN" at 7827.76,2723.7 h100
  text "6. Finish: electro-less nickel immersion gold (ENIG), 0.05-0.125um Au over 3-6um Ni - over bare copper only" at 7727.55,2569.88 h100
  text "7. Solderability test: Category 2 of J-STD-003" at 7727.76,2423.7 h100
  text "8. Finished boards shall not have nicks, scratches, voids, exposed copper, poor plating or misdrilled holes" at 7727.76,2273.7 h100
  text "9. All holes sizes are after plating" at 7727.76,2123.7 h100
  text "10. PCB manufacturer may add copper thieving as needed to improve manufacturability," at 7677.76,1973.7 h100
  text "thieving to be 0.030\" round pads at 0.050\" spacing." at 7827.76,1873.7 h100
  text "Thieving will have a minimum of 0.100\" clearance from existing copper and should not be placed under surface mounted devices" at 7827.76,1773.7 h100
  text "11. PCB manufacturer may use tear drops to improve annular rings as long as DRC rules are followed" at 7682.76,1633.7 h100
  text "12. All via connections to power and ground planes are solid" at 7682.76,1493.7 h100
  text "13. All unconnected pads on inner signal layers are removed" at 7682.76,1353.7 h100
  text "14. All finished boards are to be 100% electrically tested" at 7682.78,1213.7 h100
  text "15. Unless otherwise indicated, all linear toleracnes shall be XX.X +/-0.2mm and XX.XX +/- 0.1mm" at 7682.76,1073.7 h100
  text "16. Gerber file GM1 shows board outline (milling line)" at 7682.75,933.68 h100
  text "17. Table 1 shows Layer stack details" at 7682.75,793.67 h100
  text "18. Gerber files GTP ans DBP shows stencil cut out, stencil should be flat with no bent tabs on sides." at 7682.75,636.19 h100
  text "Symbol" at 7589.39,-1333.67 h72
  text "Count" at 8095.27,-1333.67 h72
  text "Hole Size" at 8745.09,-1333.67 h72
  text "Plated" at 9894.76,-1333.67 h72
  text "Hole Type" at 10400.63,-1333.67 h72
  text "Hole Length" at 11134.43,-1333.67 h72
  text "8" at 8095.27,-1483.67 h60
  text "19.69mil (0.500mm)" at 8745.09,-1483.67 h60
  text "PTH" at 9894.76,-1483.67 h60
  text "Round" at 10400.63,-1483.67 h60
  text "-" at 11134.43,-1483.67 h60
  text "9" at 8095.27,-1633.67 h60
  text "157.00mil (3.988mm)" at 8745.09,-1633.67 h60
  text "PTH" at 9894.76,-1633.67 h60
  text "Round" at 10400.63,-1633.67 h60
  text "-" at 11134.43,-1633.67 h60
  text "16" at 8095.27,-1783.67 h60
  text "110.24mil (2.800mm)" at 8745.09,-1783.67 h60
  text "PTH" at 9894.76,-1783.67 h60
  text "Round" at 10400.63,-1783.67 h60
  text "-" at 11134.43,-1783.67 h60
  text "42" at 8095.27,-1933.67 h60
  text "76.00mil (1.930mm)" at 8745.09,-1933.67 h60
  text "PTH" at 9894.76,-1933.67 h60
  text "Round" at 10400.63,-1933.67 h60
  text "-" at 11134.43,-1933.67 h60
  text "385" at 8095.27,-2083.67 h60
  text "11.81mil (0.300mm)" at 8745.09,-2083.67 h60
  text "PTH" at 9894.76,-2083.67 h60
  text "Round" at 10400.63,-2083.67 h60
  text "-" at 11134.43,-2083.67 h60
  text "508" at 8095.27,-2233.67 h60
  text "30.00mil (0.762mm)" at 8745.09,-2233.67 h60
  text "PTH" at 9894.76,-2233.67 h60
  text "Round" at 10400.63,-2233.67 h60
  text "-" at 11134.43,-2233.67 h60
  text "768" at 8095.27,-2383.67 h60
  text "39.37mil (1.000mm)" at 8745.09,-2383.67 h60
  text "PTH" at 9894.76,-2383.67 h60
  text "Round" at 10400.63,-2383.67 h60
  text "-" at 11134.43,-2383.67 h60
  text "1736 Total" at 8095.27,-2533.67 h60
  text "Layer" at 7540.2,-2823.89 h60
  text "Name" at 7950.11,-2823.89 h60
  text "Material" at 8879.85,-2823.89 h60
  text "Thickness" at 9739.62,-2823.89 h60
  text "Constant" at 10389.45,-2823.89 h60
  text "Board Layer Stack" at 10959.32,-2823.89 h60
  text "1" at 7540.2,-2943.89 h60
  text "Top Overlay" at 7950.11,-2943.89 h60
  text "2" at 7540.2,-3063.89 h60
  text "Top Solder" at 7950.11,-3063.89 h60
  text "Solder Resist" at 8879.85,-3063.89 h60
  text "0.40mil" at 9739.62,-3063.89 h60
  text "3.5" at 10389.45,-3063.89 h60
  text "3" at 7540.2,-3183.89 h60
  text "Top Signal" at 7950.11,-3183.89 h60
  text "Copper" at 8879.85,-3183.89 h60
  text "2.70mil" at 9739.62,-3183.89 h60
  text "4" at 7540.2,-3303.89 h60
  text "Dielectric 1" at 7950.11,-3303.89 h60
  text "FR-4" at 8879.85,-3303.89 h60
  text "10.00mil" at 9739.62,-3303.89 h60
  text "4.2" at 10389.45,-3303.89 h60
  text "5" at 7540.2,-3423.89 h60
  text "3.3 Volt" at 7950.11,-3423.89 h60
  text "Copper" at 8879.85,-3423.89 h60
  text "2.70mil" at 9739.62,-3423.89 h60
  text "6" at 7540.2,-3543.89 h60
  text "Dielectric2" at 7950.11,-3543.89 h60
  text "FR-4" at 8879.85,-3543.89 h60
  text "10.00mil" at 9739.62,-3543.89 h60
  text "4.2" at 10389.45,-3543.89 h60
  text "7" at 7540.2,-3663.89 h60
  text "GND" at 7950.11,-3663.89 h60
  text "Copper" at 8879.85,-3663.89 h60
  text "2.70mil" at 9739.62,-3663.89 h60
  text "8" at 7540.2,-3783.89 h60
  text "Dielectric 5" at 7950.11,-3783.89 h60
  text "FR-4" at 8879.85,-3783.89 h60
  text "10.00mil" at 9739.62,-3783.89 h60
  text "4.2" at 10389.45,-3783.89 h60
  text "9" at 7540.2,-3903.89 h60
  text "5 Volt" at 7950.11,-3903.89 h60
  text "Copper" at 8879.85,-3903.89 h60
  text "2.70mil" at 9739.62,-3903.89 h60
  text "10" at 7540.2,-4023.89 h60
  text "Dielectric 6" at 7950.11,-4023.89 h60
  text "FR-4" at 8879.85,-4023.89 h60
  text "10.00mil" at 9739.62,-4023.89 h60
  text "4.2" at 10389.45,-4023.89 h60
  text "11" at 7540.2,-4143.89 h60
  text "Split Plane" at 7950.11,-4143.89 h60
  text "Copper" at 8879.85,-4143.89 h60
  text "2.70mil" at 9739.62,-4143.89 h60
  text "12" at 7540.2,-4263.89 h60
  text "Dielectric3" at 7950.11,-4263.89 h60
  text "FR-4" at 8879.85,-4263.89 h60
  text "10.00mil" at 9739.62,-4263.89 h60
  text "4.2" at 10389.45,-4263.89 h60
  text "13" at 7540.2,-4383.89 h60
  text "Bot Signal" at 7950.11,-4383.89 h60
  text "Copper" at 8879.85,-4383.89 h60
  text "2.70mil" at 9739.62,-4383.89 h60
  text "14" at 7540.2,-4503.89 h60
  text "Bottom Solder" at 7950.11,-4503.89 h60
  text "Solder Resist" at 8879.85,-4503.89 h60
  text "0.40mil" at 9739.62,-4503.89 h60
  text "3.5" at 10389.45,-4503.89 h60
  text "15" at 7540.2,-4623.89 h60
  text "Bottom Overlay" at 7950.11,-4623.89 h60

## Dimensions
-237,-5173 to 4882.97,-5173 on Mechanical 1
148.83,-5031.5 to -237,-5173 on Mechanical 1
148.83,-5031.5 to -237,-5173 on Mechanical 1
140.07,-4395.42 to -237,-5173 on Mechanical 1
140.07,-4395.42 to -237,-5173 on Mechanical 1
-157.48,-708.54 to -237,-5173 on Mechanical 1
140.07,854.58 to -237,5177 on Mechanical 1
141.09,4397.89 to -237,-5173 on Mechanical 1
-157.48,-708.54 to -237,-5173 on Mechanical 1
148.83,5031.5 to -237,5177 on Mechanical 1
148.83,5031.5 to -237,-5173 on Mechanical 1
941.09,4397.89 to -237,5177 on Mechanical 1
1741.09,4397.89 to -237,5177 on Mechanical 1
2541.09,4397.89 to -237,5177 on Mechanical 1
3348.83,5031.5 to -237,5177 on Mechanical 1
642.52,-708.54 to -237,-5173 on Mechanical 1
1442.52,-708.54 to -237,-5173 on Mechanical 1
2242.52,-708.54 to -237,-5173 on Mechanical 1
4882.97,5018.28 to 4497.14,5163.78 on Mechanical 1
